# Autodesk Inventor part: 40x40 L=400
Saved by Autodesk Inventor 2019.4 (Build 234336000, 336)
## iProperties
Created: 2020-04
Part Number: 40x40 L=400
Material: Generic
Document SubType Name: Modeling
Designer: Administrator
Density: 1 g/cm^3
Appearance: Default
Title: 40x40 L=400 v4
Author: Administrator
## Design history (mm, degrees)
feature "Body2"
body "Solid1"
